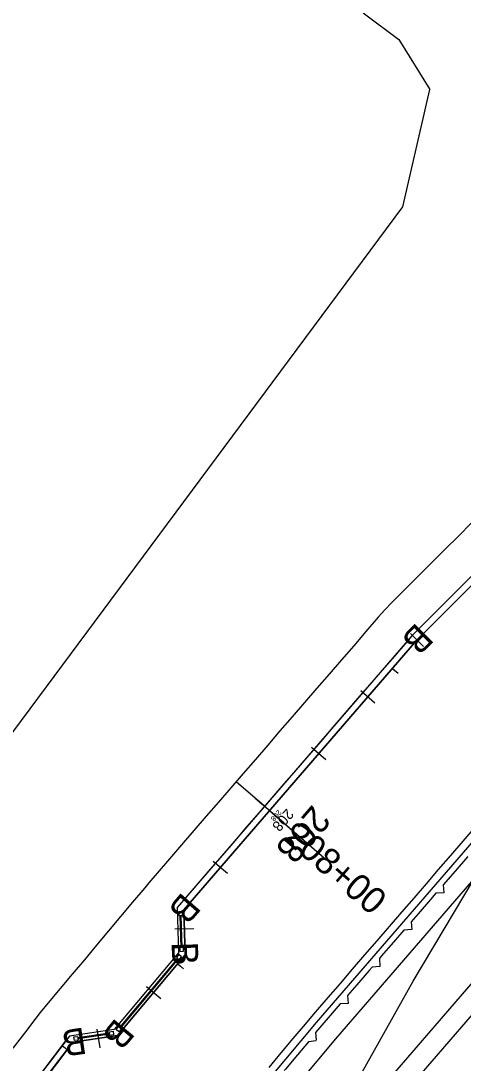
# Model space of a CAD drawing. Extents: x 1823824 to 1861612, y 706975 to 726130.
# Drawn here: x 1824788.8 to 1824906.5, y 711977.8 to 712255.1 of the extents above; entities that cross this region are included whole.
import ezdxf

# ---------------------------------------------------------------- set-up
doc = ezdxf.new("R2010")
doc.units = 0
for name, color, linetype in [('DR_X_Flood_Boundary', 7, 'Continuous'), ('GE_X_CL_10', 7, 'Continuous'), ('GE_X_CL_100', 7, 'Continuous'), ('GE_X_CL_20', 7, 'Continuous'), ('GE_X_CL_200', 7, 'Continuous'), ('GE_X_CL_50', 7, 'Continuous'), ('RW_X_Esmt_FL', 7, 'Continuous'), ('SC_Scratch1', 7, 'Continuous'), ('SC_Scratch3', 7, 'Continuous'), ('SC_Scratch5', 7, 'Continuous'), ('SC_Scratch6', 7, 'Continuous')]:
    doc.layers.add(name, color=color, linetype=linetype)

msp = doc.modelspace()

# ---------------------------------------------------------------- linework, layer by layer
at = {"layer": 'DR_X_Flood_Boundary'}
for p, q in [((1824978.6, 712174.93), (1824894.12, 712090.29)), ((1824894.12, 712090.29), (1824832.18, 712018.58)), ((1824832.18, 712018.58), (1824832.54, 712006.56)), ((1824832.54, 712006.56), (1824814.57, 711985.09)), ((1824802.7, 711983.32), (1824754.44, 711920.25)), ((1824814.57, 711985.09), (1824802.7, 711983.32))]:
    msp.add_line(p, q, dxfattribs=at)
at = {"layer": 'GE_X_CL_10'}
for p, q in [((1824887.66, 712082.81), (1824888.42, 712082.16)), ((1824854.98, 712044.98), (1824855.74, 712044.32)), ((1824830.55, 712004.19), (1824831.32, 712003.54))]:
    msp.add_line(p, q, dxfattribs=at)
at = {"layer": 'GE_X_CL_100'}
msp.add_line((1824854.98, 712044.98), (1824862.55, 712038.44), dxfattribs=at)
at = {"layer": 'GE_X_CL_20'}
for p, q in [((1824887.66, 712082.81), (1824889.18, 712081.51)), ((1824854.98, 712044.98), (1824856.49, 712043.67)), ((1824830.55, 712004.19), (1824832.09, 712002.9))]:
    msp.add_line(p, q, dxfattribs=at)
at = {"layer": 'GE_X_CL_200'}
msp.add_line((1824854.98, 712044.98), (1824870.11, 712031.9), dxfattribs=at)
at = {"layer": 'GE_X_CL_50'}
msp.add_line((1824854.98, 712044.98), (1824858.76, 712041.71), dxfattribs=at)
at = {"layer": 'RW_X_Esmt_FL'}
for p, q in [((1824879.92, 712257.3), (1824889.34, 712250.21)), ((1824889.34, 712250.21), (1824897.66, 712236.91)), ((1824890.45, 712205.63), (1824897.66, 712236.91)), ((1824646.86, 711877.55), (1824890.45, 712205.63))]:
    msp.add_line(p, q, dxfattribs=at)
at = {"layer": 'SC_Scratch1'}
for p, q in [((1824901.17, 712025.24), (1824901.33, 712023.14)), ((1824901.33, 712023.14), (1824899.23, 712022.99)), ((1824892.69, 712015.42), (1824892.84, 712013.32)), ((1824892.84, 712013.32), (1824890.75, 712013.17)), ((1824884.21, 712005.6), (1824884.36, 712003.5)), ((1824884.36, 712003.5), (1824882.26, 712003.35)), ((1824875.73, 711995.78), (1824875.88, 711993.68)), ((1824875.88, 711993.68), (1824873.78, 711993.53)), ((1824867.24, 711985.97), (1824867.43, 711983.87)), ((1824867.43, 711983.67), (1824865.33, 711983.48))]:
    msp.add_line(p, q, dxfattribs=at)
for points in [[(1824837.54, 711922.74), (1824848.43, 711918.74), (1824860.1, 711923.16), (1824873.6, 711947.64), (1824870.6, 711959.21), (1824893.22, 711999.63), (1824920.18, 712044.82), (1824961.46, 712108.81), (1824989.89, 712150.42), (1824991.25, 712152.45), (1825003.05, 712154.01), (1825020.13, 712176.93), (1825019.11, 712188.57), (1825068.43, 712250.92), (1825080.52, 712252.77), (1825099.08, 712274.14), (1825098.5, 712286.03), (1825161.91, 712356.25)], [(1824837.54, 711922.74), (1824848.43, 711918.74), (1824860.1, 711923.16), (1824873.6, 711947.64), (1824870.6, 711959.21), (1824893.22, 711999.63), (1824920.18, 712044.82), (1824961.46, 712108.81), (1824989.89, 712150.42), (1824991.25, 712152.45), (1825003.05, 712154.01), (1825020.13, 712176.93), (1825019.11, 712188.57), (1825068.43, 712250.92), (1825080.52, 712252.77), (1825099.08, 712274.14), (1825098.5, 712286.03), (1825161.91, 712356.25)], [(1825105.72, 712238.1), (1825041.58, 712175.28), (1825012.05, 712142.98), (1824928.03, 712058.8), (1824867.42, 711988.62), (1824838.82, 711954.42), (1824791.58, 711892.69), (1824765.73, 711856.76), (1824735.96, 711811.35), (1824706.1, 711762.93), (1824677.47, 711714.29), (1824651.68, 711665.89), (1824630.67, 711625.89), (1824564.54, 711490.46), (1824542.7, 711439.44)], [(1825110.13, 712232.99), (1825046.42, 712170.6), (1825016.92, 712138.33), (1824932.97, 712054.22), (1824872.55, 711984.27), (1824844.08, 711950.22), (1824796.99, 711888.68), (1824771.28, 711852.95), (1824741.64, 711807.74), (1824711.87, 711759.46), (1824683.34, 711710.99), (1824657.63, 711662.75), (1824636.68, 711622.85), (1824570.66, 711487.65), (1824551.08, 711441.92)], [(1825121.76, 712219.53), (1825059.19, 712158.26), (1825029.76, 712126.06), (1824945.98, 712042.13), (1824886.07, 711972.77), (1824857.94, 711939.13), (1824811.24, 711878.1), (1824785.91, 711842.89), (1824756.62, 711798.22), (1824727.07, 711750.3), (1824698.83, 711702.31), (1824673.32, 711654.44), (1824652.51, 711614.83), (1824615.99, 711540.02)], [(1825125.32, 712215.32), (1825063.14, 712154.44), (1825033.74, 712122.26), (1824950.02, 712038.39), (1824890.27, 711969.21), (1824862.23, 711935.69), (1824815.66, 711874.82), (1824790.44, 711839.78), (1824761.26, 711795.26), (1824731.78, 711747.46), (1824703.63, 711699.63), (1824678.18, 711651.87), (1824657.42, 711612.34), (1824626.24, 711548.48)], [(1824908.75, 712121.59), (1824905.22, 712118.05), (1824901.69, 712114.51), (1824898.16, 712110.97), (1824894.62, 712107.43), (1824891.09, 712103.89), (1824887.56, 712100.35), (1824885.63, 712098.42), (1824883.9, 712096.44), (1824880.63, 712092.65), (1824877.37, 712088.87), (1824874.1, 712085.09), (1824870.83, 712081.3), (1824867.56, 712077.52), (1824864.29, 712073.73), (1824861.03, 712069.95), (1824857.76, 712066.17), (1824854.49, 712062.38), (1824851.22, 712058.6), (1824847.95, 712054.81), (1824844.68, 712051.03), (1824841.42, 712047.25), (1824838.15, 712043.46), (1824834.88, 712039.68), (1824831.61, 712035.9), (1824828.34, 712032.11), (1824825.07, 712028.33), (1824822.85, 712025.75), (1824821.77, 712024.47), (1824818.57, 712020.63), (1824815.36, 712016.8), (1824812.15, 712012.97), (1824808.94, 712009.13), (1824805.73, 712005.3), (1824802.52, 712001.46), (1824799.31, 711997.63), (1824796.1, 711993.79), (1824793.99, 711991.27), (1824792.81, 711989.74), (1824789.77, 711985.77), (1824786.74, 711981.8)], [(1824908.77, 712107.44), (1824905.23, 712103.9), (1824901.7, 712100.37), (1824898.17, 712096.83), (1824894.64, 712093.29), (1824892.71, 712091.36), (1824891.47, 712089.9), (1824888.2, 712086.12), (1824884.93, 712082.33), (1824881.67, 712078.55), (1824878.4, 712074.77), (1824875.13, 712070.98), (1824871.86, 712067.2), (1824868.59, 712063.41), (1824865.32, 712059.63), (1824862.06, 712055.85), (1824858.79, 712052.06), (1824855.52, 712048.28), (1824852.25, 712044.49), (1824848.98, 712040.71), (1824845.72, 712036.93), (1824842.45, 712033.14), (1824839.18, 712029.36), (1824835.91, 712025.57), (1824832.64, 712021.79), (1824830.42, 712019.21), (1824830.41, 712019.21)], [(1824909.69, 712040.62), (1824906.42, 712036.83), (1824903.15, 712033.05), (1824899.88, 712029.27), (1824896.61, 712025.48), (1824893.34, 712021.7), (1824890.08, 712017.91), (1824886.81, 712014.13), (1824883.54, 712010.35), (1824880.27, 712006.56), (1824877, 712002.78), (1824873.73, 711998.99), (1824870.47, 711995.21), (1824867.2, 711991.43), (1824865.67, 711989.66), (1824864.42, 711988.15), (1824861.21, 711984.32), (1824858, 711980.48), (1824854.8, 711976.65)], [(1824907.71, 712032.81), (1824907.6, 712032.68), (1824904.33, 712028.9), (1824901.17, 712025.24)], [(1824899.23, 712022.99), (1824897.8, 712021.33), (1824894.53, 712017.55), (1824892.69, 712015.42)], [(1824890.75, 712013.17), (1824887.99, 712009.98), (1824884.72, 712006.2), (1824884.21, 712005.6)], [(1824882.26, 712003.35), (1824881.45, 712002.41), (1824878.19, 711998.63), (1824875.73, 711995.78)], [(1824873.78, 711993.53), (1824871.65, 711991.06), (1824868.38, 711987.28), (1824867.24, 711985.96)], [(1824801.74, 711984.95), (1824801.66, 711984.85), (1824800.75, 711983.67), (1824797.72, 711979.7), (1824794.68, 711975.72), (1824791.64, 711971.75), (1824788.6, 711967.78), (1824785.56, 711963.81), (1824782.53, 711959.84), (1824779.49, 711955.87), (1824776.45, 711951.9), (1824773.41, 711947.93), (1824770.37, 711943.96), (1824767.33, 711939.99), (1824764.3, 711936.01), (1824761.26, 711932.04), (1824758.22, 711928.07), (1824755.18, 711924.1), (1824752.63, 711920.76)], [(1824865.33, 711983.48), (1824862.39, 711979.97), (1824859.19, 711976.13), (1824858.92, 711975.81)]]:
    msp.add_lwpolyline(points, dxfattribs=at)
at = {"layer": 'SC_Scratch3'}
for p, q in [((1824853.65, 712046.12), (1824846.09, 712052.66)), ((1824833.81, 712020.47), (1824832.49, 712021.61)), ((1824831.82, 712018.08), (1824830.82, 712018.05)), ((1824830.82, 712018.05), (1824830.85, 712017.05)), ((1824830.85, 712017.05), (1824831.85, 712017.08)), ((1824831.48, 712008.53), (1824831.22, 712017.06)), ((1824831.73, 712008.53), (1824831.47, 712017.07)), ((1824831.85, 712017.08), (1824831.82, 712018.08)), ((1824832.1, 712008.55), (1824831.1, 712008.51)), ((1824831.1, 712008.51), (1824831.13, 712007.51)), ((1824832.13, 712007.54), (1824832.1, 712008.55)), ((1824830.49, 712005.66), (1824815.08, 711987.26)), ((1824830.68, 712005.5), (1824815.27, 711987.1)), ((1824830.84, 712006.67), (1824830.2, 712005.91)), ((1824830.2, 712005.91), (1824830.97, 712005.26)), ((1824831.61, 712006.03), (1824830.84, 712006.67)), ((1824830.97, 712005.26), (1824831.61, 712006.03)), ((1824831.13, 712007.51), (1824832.13, 712007.54)), ((1824825.49, 711999.31), (1824825.3, 711999.47)), ((1824825.6, 711999.43), (1824825.4, 711999.59)), ((1824820.35, 711993.17), (1824820.16, 711993.33)), ((1824820.46, 711993.3), (1824820.27, 711993.46)), ((1824812.39, 711986.15), (1824813.38, 711986.3)), ((1824812.53, 711985.16), (1824812.39, 711986.15)), ((1824813.38, 711986.3), (1824813.52, 711985.31)), ((1824814.15, 711986.73), (1824814.8, 711987.5)), ((1824814.92, 711986.09), (1824814.15, 711986.73)), ((1824814.8, 711987.5), (1824815.56, 711986.86)), ((1824815.56, 711986.86), (1824814.92, 711986.09)), ((1824802.95, 711984.75), (1824803.94, 711984.9)), ((1824803.09, 711983.76), (1824802.95, 711984.75)), ((1824804.08, 711983.91), (1824803.09, 711983.76)), ((1824803.94, 711984.9), (1824804.08, 711983.91)), ((1824812.44, 711985.78), (1824803.99, 711984.53)), ((1824812.48, 711985.53), (1824804.03, 711984.28)), ((1824813.52, 711985.31), (1824812.53, 711985.16)), ((1824801.18, 711981.34), (1824799.79, 711982.4))]:
    msp.add_line(p, q, dxfattribs=at)
for points in [[(1825072.21, 712272.45), (1825008.3, 712207.43), (1825011.73, 712194.9), (1824990.64, 712173.59), (1824978.07, 712176.88), (1824892.84, 712091.49), (1824830.41, 712019.21), (1824830.77, 712007.17), (1824813.65, 711986.72), (1824801.74, 711984.95), (1824752.63, 711920.76), (1824753.86, 711908.78), (1824738.28, 711887.14), (1824726.53, 711884.51), (1824695.45, 711837.1), (1824665, 711787.73)], [(1824666.49, 711786.8), (1824696.93, 711836.18), (1824727.6, 711882.96), (1824739.31, 711885.58), (1824755.67, 711908.3), (1824754.44, 711920.25), (1824802.7, 711983.32), (1824814.57, 711985.09), (1824832.54, 712006.56), (1824832.18, 712018.58), (1824894.12, 712090.29), (1824978.6, 712174.93), (1824991.17, 712171.64), (1825013.68, 712194.38), (1825010.26, 712206.92), (1825073.72, 712271.49)]]:
    msp.add_lwpolyline(points, dxfattribs=at)
at = {"layer": 'SC_Scratch5'}
for points in [[(1824895.97, 712088.61), (1824892.44, 712092.14)], [(1824883.02, 712073.61), (1824879.23, 712076.88)], [(1824869.94, 712058.48), (1824866.16, 712061.75)], [(1824858.76, 712041.71), (1824851.2, 712048.24)], [(1824843.8, 712028.21), (1824840.01, 712031.47)], [(1824834.83, 712013.54), (1824829.83, 712013.39)], [(1824826.05, 711994.91), (1824822.22, 711998.12)], [(1824809.89, 711981.86), (1824809.16, 711986.81)]]:
    msp.add_lwpolyline(points, dxfattribs=at)

# ---------------------------------------------------------------- texts
at = {"layer": 'GE_X_CL_10'}
msp.add_text('208', height=1.4, rotation=229.1815, dxfattribs=at).set_placement((1824857.27, 712045.34))
at = {"layer": 'GE_X_CL_20'}
msp.add_text('208', height=2.8, rotation=229.1815, dxfattribs=at).set_placement((1824859.57, 712045.7))
at = {"layer": 'GE_X_CL_50'}
msp.add_text('208', height=7, rotation=229.1815, dxfattribs=at).set_placement((1824866.46, 712046.79))
at = {"layer": 'SC_Scratch5'}
msp.add_text('208+00', height=7, rotation=319.1815, dxfattribs=at).set_placement((1824858.37, 712037.42))
at = {"layer": 'SC_Scratch6'}
for rotation, p in [(225.0545, (1824894.12, 712095.24)), (229.1815, (1824831.82, 712023.51)), (271.7058, (1824828.93, 712009.95)), (230.071, (1824814.13, 711990.02)), (188.4448, (1824805.65, 711987.3))]:
    msp.add_text('B', height=7, rotation=rotation, dxfattribs=at).set_placement(p)

doc.saveas('drawing.dxf')
